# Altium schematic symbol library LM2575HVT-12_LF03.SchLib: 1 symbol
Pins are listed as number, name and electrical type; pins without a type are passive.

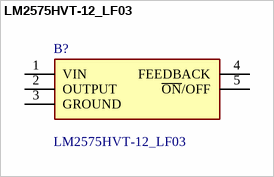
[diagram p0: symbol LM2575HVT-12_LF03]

## LM2575HVT-12_LF03
designator B?
Switching Voltage Regulators SIMPLE SWITCHER 1A Step-Down Voltage Regulator 5-TO-220; Manufacturer_Name: Texas Instruments; Manufacturer_Part_Number: LM2575HVT-12/LF03; Geometry.Height: 4.7mm
footprint TO170P470X1028X2142-5P
pins: 1 VIN, 2 OUTPUT, 3 GROUND, 4 FEEDBACK, 5 ~{ON}/OFF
